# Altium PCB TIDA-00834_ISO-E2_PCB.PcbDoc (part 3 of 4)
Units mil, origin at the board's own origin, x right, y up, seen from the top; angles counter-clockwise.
Board outline 9055.12 x 4133.86 mil, 4 copper layers (Top Layer, GND, PWR, Bottom Layer), stack 61.92 mil thick; 647 components, 282 nets, 1430 pads, 409 vias.
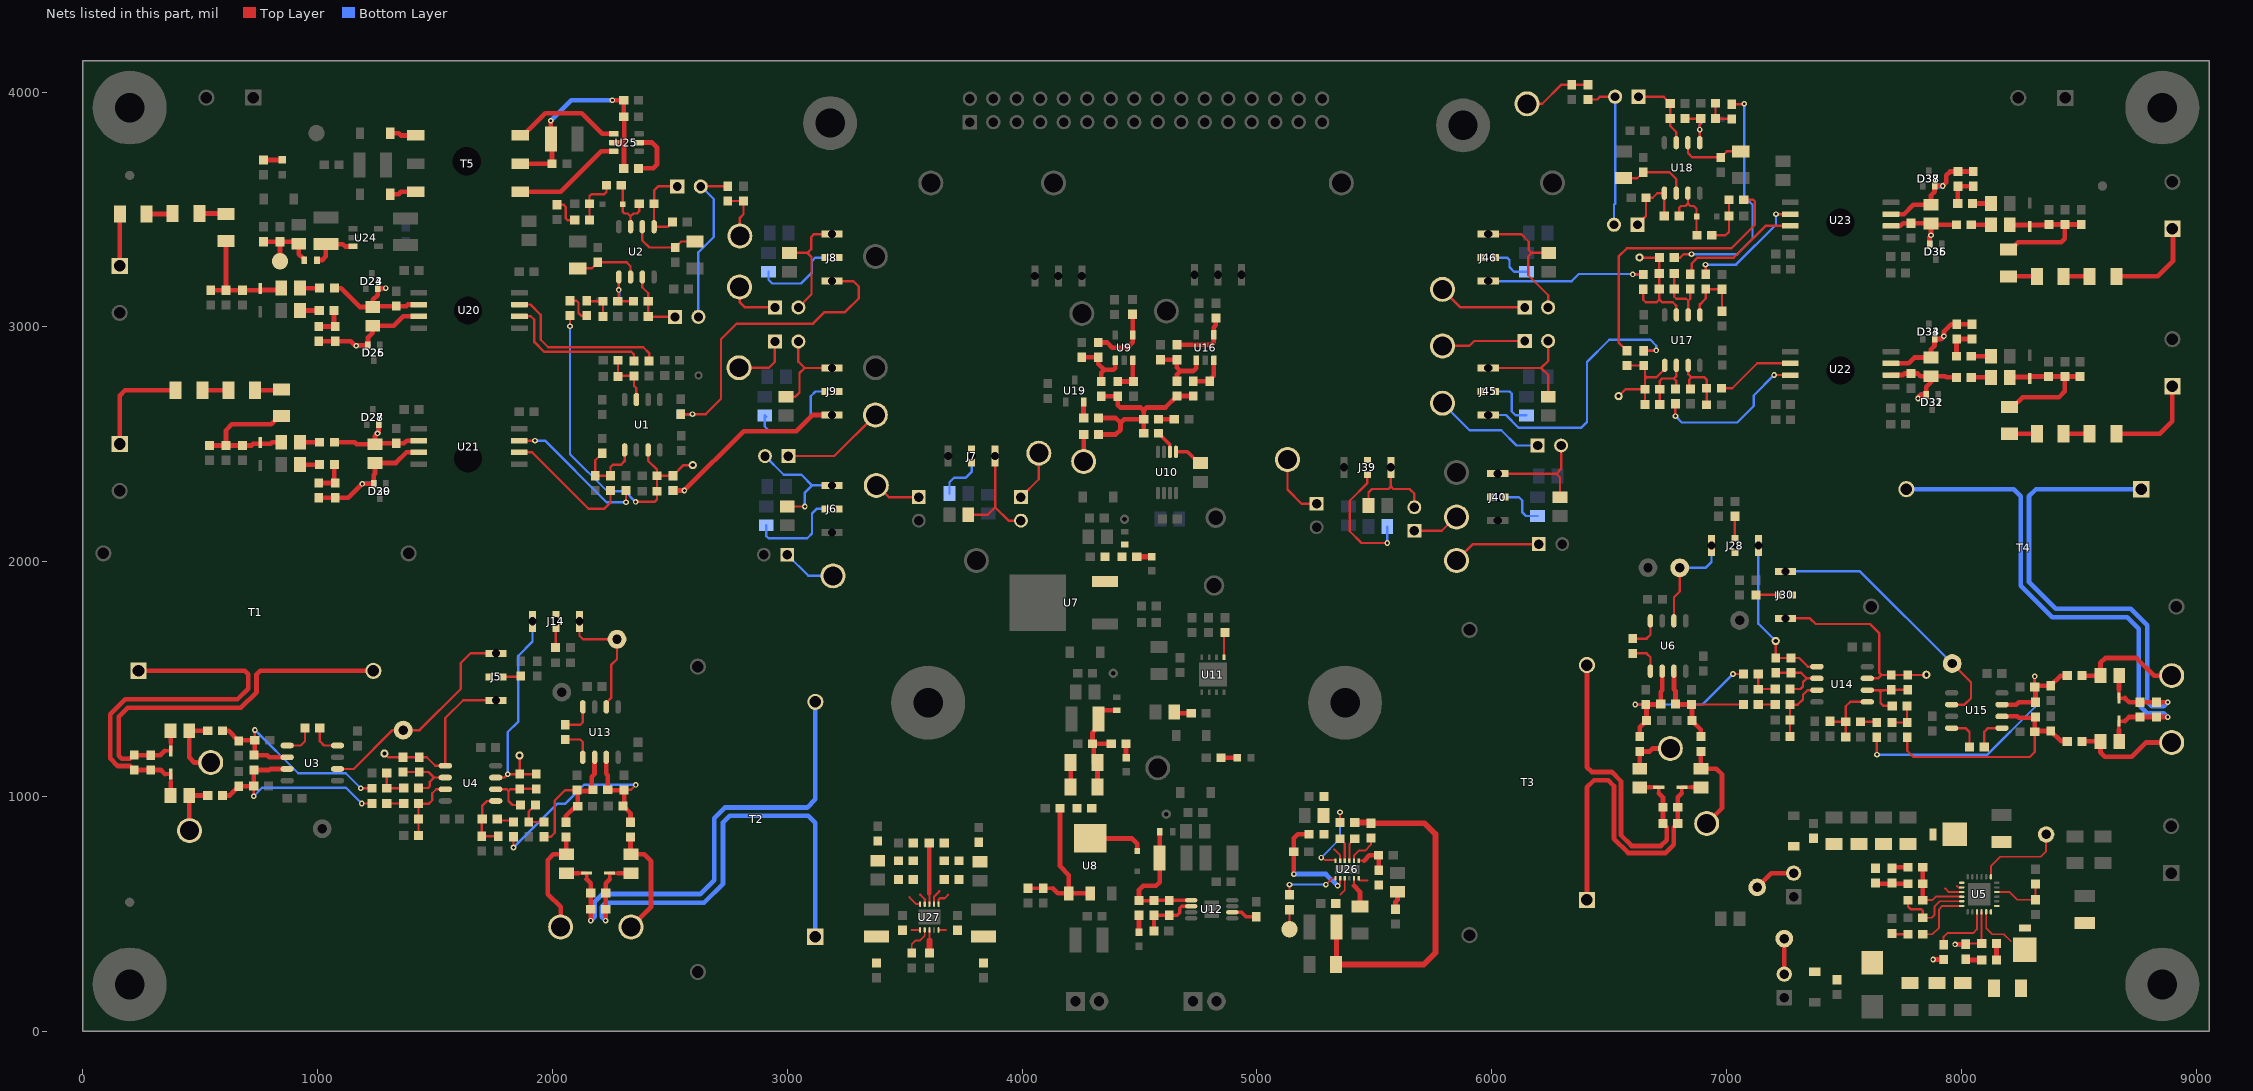
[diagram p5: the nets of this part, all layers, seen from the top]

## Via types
v1: diameter 24, hole 12, Top Layer to Bottom Layer, tented both sides, 388 vias
v2: diameter 19.68, hole 7.87, Top Layer to Bottom Layer, tented top, 15 vias
v3: diameter 19.68, hole 7.87, Top Layer to Bottom Layer, 5 vias
v4: diameter 40, hole 20, Top Layer to Bottom Layer, 1 vias

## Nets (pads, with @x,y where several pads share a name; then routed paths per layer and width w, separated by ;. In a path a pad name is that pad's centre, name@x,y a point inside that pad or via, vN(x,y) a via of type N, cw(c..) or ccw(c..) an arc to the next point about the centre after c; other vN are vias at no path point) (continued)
NetC2_2: C2.2 R3.1 R10.1 R230.2 TP4.1 U1.7 | length 1446.5
  Top Layer w10: v1(2075,3003) R230.2@2075,3048.5 ; v1(2354,2255) 2435,2255 2445,2265 R3.1@2445,2300 C2.2@2445,2366.3 ; U1.7@2407.38,2476.06 2407.38,2430.35 2445,2392.73 C2.2@2445,2366.3 ; TP4.1@2597.38,2411.49 2558.5,2411.49 R10.1@2513.5,2366.5 2513.31,2366.3 C2.2@2445,2366.3
  Bottom Layer w10: v1(2075,3003) 2075,2458 2233,2300 2309,2300 v1(2354,2255)
NetC7_2: C7.2 D1.1 L13.1 R11.1 R19.2 R20.2 | length 516.5
  Top Layer w20: R20.2@545,3156.5 R19.2@610,3156.5 ; R11.1@610,3365.83 R19.2@610,3156.5 ; C7.2@680,3156.5 C7.2@682.01,3156.5 ; L13.1@845,3165 837.02,3157.02 755.48,3157.02 754.95,3156.5 C7.2@682.01,3156.5 ; R19.2@610,3156.5 677.99,3156.5 680,3154.49 C7.2@682.01,3156.5
NetC8_2: C8.2 D2.1 L14.1 R16.1 R21.2 R22.2 | length 637.5
  Top Layer w20: R22.2@540,2495 R21.2@610,2495 ; L14.1@845,2508.5 807.01,2508.5 800.31,2501.81 725.31,2501.81 718.5,2495 C8.2@680,2495 R21.2@610,2495 ; R16.1@847.09,2619.92 836.85,2619.92 801.93,2585 635,2585 610,2560 R21.2@610,2495
NetC10_2: C10.2 R26.2 R27.1 | length 209.6
  Top Layer w10: R26.2@2157.97,3454.57 C10.2@2157.97,3524.57 2157.97,3556.89 2166.08,3565 2220,3565 2229.98,3574.98 R27.1@2229.98,3602.72
NetC11_2: C11.2 R32.2 R33.1 | length 134.1
  Top Layer w10: R32.2@2146.48,3111.07 2147.97,3109.57 R33.1@2214.98,3109.57 C11.2@2214.98,3044.57
NetC14_1: C14.1 C15.1 R35.2 R36.2 R57.2 U3.3 | length 949.7
  Top Layer w10: v1(727.91,1001.36) R36.2@727.91,1045.04 ; v1(1187.83,970.28) R57.2@1231.52,970.28
  Top Layer w20: R35.2@595,1005 625.86,1005 C14.1@664.41,1043.54 R36.2@726.41,1043.54 ; R36.2@727.91,1045.04 727.91,1112.05 C15.1@729.41,1113.54 794.41,1113.54 798.39,1117.52 U3.3@870.32,1117.52
  Bottom Layer w10: v1(727.91,1001.36) 764.74,1038.19 1119.92,1038.19 v1(1187.83,970.28)
NetC15_2: C15.2 C16.2 R40.1 R41.2 R62.2 U3.2 | length 1085
  Top Layer w10: C15.2@729.41,1176.53 729.41,1236.53 R40.1@732.91,1240.04 v1(732.91,1283.54) ; U3.2@866.81,1164.01 U3.2@870.32,1167.52 ; v1(1184.1,1035.28) R62.2@1231.52,1035.28
  Top Layer w20: R41.2@595,1280 620.94,1280 C16.2@664.41,1236.53 667.91,1240.04 R40.1@732.91,1240.04 C15.2@732.91,1180.04 ; C15.2@729.41,1176.53 786.06,1176.53 795.08,1167.52 U3.2@870.32,1167.52
  Bottom Layer w10: v1@732.91,1291.69 v1(732.91,1283.54) 917.26,1099.19 1120.18,1099.19 v1(1184.1,1035.28)
NetC19_1: C19.1 R43.2 R44.1 U4.2 | length 286.9
  Top Layer w10: R43.2@1363.09,1104.9 C19.1@1433.09,1104.9 1472.46,1104.9 1496.14,1081.22 ; R44.1@1429.59,1036.4 1470.22,1036.4 1478.09,1044.27 1478.09,1063.17 1496.14,1081.22 ; U4.2@1544,1081.22 1496.14,1081.22
NetC19_2: C19.2 J5.3 R43.1 TP10.1 U4.1 | length 731.4
  Top Layer w10: TP10.1@1284.41,1183.19 1299.7,1167.89 R43.1@1363.09,1167.89 C19.2@1433.09,1167.89 1464.47,1167.89 1501.14,1131.22 U4.1@1544,1131.22 1544,1334 1620,1410 J5.3@1760,1410
NetC25_1: C25.1 C27.1 C28.1 C29.1 C30.1 D5.1 J15.2 R58.2 R59.2 R60.2 TP15.1 | length 221
  Top Layer w8: R60.2@8017.64,307.83 R60.2@8021.14,304.33
  Top Layer w20: J15.2@7245.12,243.86 TP15.1@7245.12,394.88 ; R60.2@8021.14,304.33 R59.2@8086.14,304.33
NetC31_2: C31.2 R66.1 U5.17 | length 343.8
  Top Layer w8: C31.2@7835.12,483.86 7873.12,483.86 7885.12,495.86 7885.12,532.86 7906.39,554.13 U5.17@8000.79,554.13
  Top Layer w10: R66.1@7772.13,558.86 7772.13,531.85 7783.12,520.86 7827.89,520.86 7835.12,513.63 C31.2@7835.12,483.86
NetC32_1: C32.1 R59.1 | length 70
  Top Layer w20: R59.1@8149.13,304.33 C32.1@8149.13,374.33
NetC32_2: C32.2 R60.1 R61.1 U5.22 | length 287
  Top Layer w8: R60.1@8021.85,375.04 8085.43,375.04 U5.22@8085.43,508.86
  Top Layer w20: v1(7972.83,370.83) R60.1@8017.64,370.83
  Bottom Layer w20: v1(7972.83,370.83) R61.1@8017.64,370.83
NetC33_2: C33.2 R63.2 | length 65
  Top Layer w10: C33.2@7707.13,413.86 R63.2@7772.13,413.86
NetC34_1: C34.1 R67.1 | length 74.9
  Top Layer w10: R67.1@7703.62,695.35 R67.1@7707.13,698.86 ; C34.1@7768.62,695.35 C34.1@7772.13,698.86
  Top Layer w20: R67.1@7707.13,698.86 C34.1@7772.13,698.86
NetC34_2: C34.2 R64.1 R66.2 U5.16 | length 311.9
  Top Layer w8: R66.2@7835.12,558.86 7876.12,558.86 7891.08,573.82 U5.16@8000.79,573.82
  Top Layer w20: R66.2@7835.12,558.86 C34.2@7835.12,698.86
NetC35_1: C35.1 C36.1 C39.1 C40.1 C41.1 D6.2 D7.2 J16.2 R65.2 TP16.1 U5.15 | length 257
  Top Layer w8: 7930.12,608.86 7945.47,593.5 U5.15@8000.79,593.5
  Top Layer w20: TP16.1@7130,613.74 7190.12,673.86 J16.2@7285.12,673.86
NetC37_1: C37.1 R68.2 U5.4 | length 245.3
  Top Layer w8: U5.4@8150.39,593.5 8205.47,593.5 8238.15,560.83 C37.1@8315.12,560.83 R68.2@8315.12,627.83
NetC42_1: C42.1 R69.2 | length 89.6
  Top Layer w20: v1(7879.13,306.54) R69.2@7923.94,306.54
  Bottom Layer w20: v1(7879.13,306.54) C42.1@7923.94,306.54
NetC47_1: C47.1 C48.1 R106.2 R107.2 R113.2 U6.3 | length 586.7
  Top Layer w10: R107.2@6850.44,1392.36 R113.2@7071.55,1392.36
  Top Layer w20: U6.3@6775.43,1533.98 6775.43,1456.69 6781.93,1450.19 C48.1@6781.93,1393.86 6783.43,1392.36 R107.2@6850.44,1392.36 6851.93,1390.87 C47.1@6851.93,1323.86 6890.12,1285.67 R106.2@6890.12,1255.35 ; R113.2@7071.55,1392.36 R113.2@7071.71,1392.2
NetC48_2: C48.2 C52.2 R111.1 R112.2 R114.2 U6.2 | length 917.4
  Top Layer w10: v1(6610.44,1392.36) R111.1@6655.44,1392.36 ; v1(7026.71,1522.2) R114.2@7071.71,1522.2
  Top Layer w20: R112.2@6630.12,1255.35 6630.12,1295.04 C52.2@6658.94,1323.86 6658.94,1388.86 R111.1@6655.44,1392.36 6717.44,1392.36 C48.2@6718.94,1393.86 6718.94,1445.83 6725.43,1452.32 U6.2@6725.43,1533.98
  Bottom Layer w10: v1(6610.44,1392.36) 6896.87,1392.36 v1(7026.71,1522.2)
NetC49_1: C49.1 FB1.1 R71.2 U7.3
NetC54_1: C54.1 C59.1 C60.1 D45.2 FB2.1 R74.2 R75.2 R76.2 U8.4 | length 734.8
  Top Layer w20: U8.4@4290,822.3 4291.15,821.15 4468.85,821.15 4490,800 D45.2@4490,768.31 ; R76.2@4321,1051 4321,1126.91 4305,1142.91 4305,1219.41 C59.1@4299.41,1225 ; R74.2@4379.41,1225 C59.1@4299.41,1225 ; FB2.1@4402.91,1367.44 4325,1367.44 C60.1@4325,1330 4325,1297.09 4299.41,1271.5 C59.1@4299.41,1225
NetC54_2: C54.2 C166.1 R75.1 R76.1 R79.2 R80.2 U8.1 U8.2 | length 752.8
  Top Layer w15: R80.2@4025,610 R79.2@4090,610 4130,610
  Top Layer w20: 4130,610 4152.2,587.8 U8.1@4199,587.8 ; C166.1@4161.5,950 4161.5,703.5 4199,666 U8.1@4199,587.8 ; R76.1@4205.83,1044.17 R76.1@4205.83,1055.32 ; R76.1@4206.91,1055.32 R75.1@4206.91,1145 ; U8.2@4290,587.8 U8.1@4199,587.8
NetC61_1: C61.1 U10.5 | length 123.7
  Top Layer w15: U10.5@4654.98,2467.6 4704,2467.6 4751.6,2420 C61.1@4759,2420
NetC63_2: C63.2 R78.1 U9.3 | length 157.7
  Top Layer w20: R78.1@4407.15,2767.75 C63.2@4474,2767.75 4471.4,2770.35 U9.3@4471.4,2857.55
NetC64_1: C64.1 R81.2 | length 67
  Top Layer w20: R81.2@4580.5,2607 C64.1@4647.5,2607
NetC70_1: C70.1 R85.1 R86.2 U12.2 | length 252.7
  Top Layer w15: R86.2@4561.21,427.75 4561.44,427.99 R85.1@4561.44,494.26 C70.1@4626.44,494.26 4660.44,494.26 4671.44,505.26 4671.44,525.26 4679.24,533.06 U12.2@4719.8,533.06
NetC70_2: C70.2 C72.2 FB3.1 R84.2 R85.2 U12.1 | length 584.2
  Top Layer w15: R84.2@4497.71,557.25 R85.2@4561.44,557.25 4562.84,558.65 U12.1@4719.8,558.65
  Top Layer w20: R84.2@4497.71,557.25 4497.71,602.71 4515,620 4570,620 4585.62,635.62 C72.2@4585.62,737.75 FB3.1@4585.62,850.13
NetC73_1: C73.1 R83.1 | length 74.3
  Top Layer w20: C73.1@4647.4,1360 4652.4,1355 R83.1@4719.61,1355
NetC74_2: C74.2 U12.6 | length 109.2
  Top Layer w15: U12.6@4895,507.47 4934.24,507.47 4952.94,488.77 C74.2@4996.44,488.77
NetC77_1: C77.1 C78.1 R89.2 R90.2 R104.2 U13.3 | length 1098.1
  Top Layer w10: v1(1834.41,783.19) R104.2@1834.41,828.6 ; R90.2@2304.41,1027.59 2305.91,1029.09 2334.09,1029.09 v1(2355,1050)
  Top Layer w20: U13.3@2229.41,1167.36 2229.41,1097.02 2235.91,1090.53 C78.1@2235.91,1029.09 2237.4,1027.59 R90.2@2304.41,1027.59 2305.91,1026.1 C77.1@2305.91,959.09 ; C77.1@2300.91,960.04 2332.35,928.6 R89.2@2332.35,890.58
  Bottom Layer w10: v1(1834.41,783.19) 2021.22,970 2055,970 2135,1050 v1(2355,1050)
NetC78_2: C78.2 C79.2 R94.1 R95.2 R105.2 U13.2 | length 670.5
  Top Layer w10: R105.2@1964.41,828.54 1992.54,828.54 2010,846 2010,983.18 2054.41,1027.59 R94.1@2104.41,1027.59
  Top Layer w20: R95.2@2057.35,890.58 2057.35,917.35 2099.09,959.09 C79.2@2107.92,959.09 2107.92,1024.09 2167.92,1024.09 2167.92,1084.66 2179.41,1096.15 U13.2@2179.41,1167.36
NetC82_1: C82.1 R97.2 R98.1 U4.6 | length 280.2
  Top Layer w10: U4.6@1758.57,1031.22 1806.14,1031.22 1813.09,1024.27 ; R98.1@1864.45,964.27 1830.09,964.27 1813.09,981.27 1813.09,1024.27 ; R97.2@1930.94,1032.78 C82.1@1860.94,1032.78 1859.44,1031.27 1820.09,1031.27 1813.09,1024.27
NetC82_2: C82.2 J14.3 R97.1 TP30.1 U4.7 | length 952.7
  Top Layer w10: U4.7@1758.57,1081.22 1796.22,1081.22 v1(1810,1095) 1860.18,1095 C82.2@1860.94,1095.77 ; TP30.1@1860,1175 1860.94,1174.06 C82.2@1860.94,1095.77 ; R97.1@1930.94,1095.77 C82.2@1860.94,1095.77
  Bottom Layer w10: v1(1810,1095) 1810,1275 1855,1320 1855,1600 1915,1660 J14.3@1915,1746.14
NetC88_1: C88.1 R115.2 R117.1 U14.2 | length 285.9
  Top Layer w10: R115.2@7208.82,1527.36 7272.76,1527.36 C88.1@7273.29,1526.83 7317.15,1526.83 7340.83,1503.15 ; R117.1@7269.78,1458.32 7314.58,1458.32 7325.12,1468.86 7325.12,1487.44 7340.83,1503.15 ; U14.2@7384.2,1503.15 7340.83,1503.15
NetC88_2: C88.2 J28.3 R115.1 TP28.1 U14.1 | length 699.8
  Top Layer w10: TP28.1@7208.82,1662.56 R115.1@7208.82,1590.35 7209.35,1589.82 C88.2@7273.29,1589.82 7309.15,1589.82 7345.83,1553.15 U14.1@7384.2,1553.15
  Bottom Layer w10: J28.3@7135.12,2068.86 7135.12,1736.26 TP28.1@7208.82,1662.56
NetC94_1: C94.1 C95.1 R122.2 R123.2 R129.2 U15.3 | length 1377.4
  Top Layer w10: R129.2@7638.82,1252.36 7638.82,1180.16 v1(7640.12,1178.86) ; R123.2@8311.61,1466.65 v1(8311.61,1511.65)
  Top Layer w20: U15.3@8172.4,1391.65 8232.91,1391.65 8243.43,1402.17 C95.1@8315.12,1402.17 8315.12,1463.15 R123.2@8311.61,1466.65 8317.13,1472.17 C94.1@8380.12,1472.17 8380.12,1473.39 8421.73,1515 R122.2@8450,1515
  Bottom Layer w10: v1(7640.12,1178.86) 8110.12,1178.86 8311.61,1380.35 v1(8311.61,1511.65)
NetC95_2: C95.2 C96.2 R127.1 R128.2 R130.2 U15.2 | length 1064.9
  Top Layer w10: R130.2@7768.82,1252.36 7768.82,1195.16 7795.12,1168.86 8290.12,1168.86 8311.61,1190.35 R127.1@8311.61,1275.67
  Top Layer w20: U15.2@8172.4,1341.65 8237.32,1341.65 8243.31,1335.67 8311.61,1335.67 R127.1@8311.61,1275.67 8315.12,1279.18 C96.2@8380.12,1279.18 8424.3,1235 R128.2@8450,1235
NetC99_1: C99.1 R131.2 R133.1 U14.6 | length 299.1
  Top Layer w10: U14.6@7598.77,1453.15 7664.41,1453.15 ; 7645.83,1453.15 7655.12,1443.86 ; R133.1@7704.65,1386.2 7667.78,1386.2 7655.12,1398.86 7655.12,1443.86 ; R131.2@7771.14,1454.7 C99.1@7701.14,1454.7 7699.59,1453.15 7664.41,1453.15 ; 7655.12,1443.86 7664.41,1453.15
NetC99_2: C99.2 J30.3 R131.1 TP41.1 U14.7 | length 865.2
  Top Layer w10: J30.3@7250.12,1758.86 7355,1758.86 7378.86,1735 7610,1735 7650.12,1694.88 7650.12,1526.53 7658.95,1517.69 ; U14.7@7598.77,1503.15 7644.41,1503.15 7658.95,1517.69 ; TP41.1@7850.12,1518.86 7848.95,1517.69 R131.1@7771.14,1517.69 C99.2@7701.14,1517.69 7658.95,1517.69
NetC101_1: C101.1 R138.2 R143.1 U17.2 | length 275.5
  Top Layer w10: R138.2@6714.86,2669.33 C101.1@6714.86,2734.33 6714.86,2769.86 6725,2780 6775,2780 ; R143.1@6781.71,2735.82 6785,2739.11 6785,2770 6775,2780 ; U17.2@6785.96,2836.42 6785.96,2790.96 6775,2780
NetC101_2: C101.2 R138.1 R145.1 R200.2 TP44.1 U17.1 | length 487.2
  Top Layer w10: TP44.1@6540,2705 6569.33,2734.33 C101.2@6651.87,2734.33 ; R200.2@6575,2835.55 R145.1@6647.26,2835.55 ; R138.1@6651.87,2669.33 C101.2@6651.87,2734.33 ; 6651.87,2793.13 6660,2785 ; R145.1@6651.87,2830.94 6651.87,2776.87 ; U17.1@6735.96,2836.42 6735.96,2820.96 6700,2785 6660,2785 ; C101.2@6651.87,2734.33 6651.87,2776.87 ; 6651.87,2776.87 6660,2785
NetC102_1: C102.1 R140.2 R146.1 U17.6 | length 278.9
  Top Layer w10: R140.2@6776.33,3227.04 C102.1@6776.33,3160.74 6776.33,3128.67 6785,3120 6826.91,3120 6835.96,3110.96 ; U17.6@6835.96,3050.98 6835.96,3110.96 ; R146.1@6844.84,3160.86 6844.84,3119.84 6835.96,3110.96
NetC102_2: C102.2 R140.1 R147.1 R201.2 TP45.1 U17.7 | length 508.4
  Top Layer w10: TP45.1@6629,3296 6630,3295 R201.2@6713.5,3295 6713.34,3294.84 R140.1@6713.34,3227.04 C102.2@6713.34,3160.74 6713.34,3116.66 ; R147.1@6644.84,3160.55 6644.84,3115.16 6655,3105 6701.68,3105 6713.34,3116.66 ; U17.7@6785.96,3050.98 6785.96,3089.04 6770,3105 6725,3105 6713.34,3116.66
NetC107_2: C107.2 D17.1 L17.1 R148.1 R156.2 R157.2 | length 627.2
  Top Layer w20: R148.1@8205,2659.17 8219.17,2659.17 8260,2700 8415,2700 8440,2725 R156.2@8440,2788.5 ; L17.1@8205,2785 8206.69,2786.69 8290,2786.69 8291.81,2788.5 C107.2@8370,2788.5 R156.2@8440,2788.5 ; R157.2@8505,2788.5 R156.2@8440,2788.5
NetC108_2: C108.2 D18.1 L18.1 R153.1 R158.2 R159.2 | length 623.4
  Top Layer w20: R153.1@8199.96,3329.61 8210.2,3329.61 8240.59,3360 8425,3360 8440,3375 R158.2@8440,3435.98 ; L18.1@8205,3435 8205.83,3434.17 C108.2@8371.14,3434.17 ; C108.2@8372.95,3435.98 R158.2@8440,3435.98 ; R159.2@8510,3435.98 R158.2@8440,3435.98
NetC109_2: C109.2 R163.2 R164.1 | length 216.2
  Top Layer w10: R164.1@6936.5,3390 6995,3390 7009.63,3404.63 C109.2@7009.63,3471.84 R163.2@7009.63,3541.68
NetC111_2: C111.2 R169.2 R170.1 | length 134.2
  Top Layer w10: C111.2@6952.62,3951.84 R170.1@6952.62,3886.84 7019.47,3886.84 R169.2@7021.12,3885.19
NetC117_2: C117.2 R192.1 U16.3 | length 166.6
  Top Layer w20: R192.1@4729,2768.5 C117.2@4799,2768.5 4799,2775 4816.4,2792.4 U16.3@4816.4,2857.87
NetC120_2: C120.2 R196.2 TP31.1 | length 222.4
  Top Layer w10: R196.2@2746.48,3536.22 2813.09,3536.22 C120.2@2813.52,3535.79 2813.52,3479.52 2798,3464 TP31.1@2798,3387
NetC121_2: C121.2 R197.2 TP46.1 | length 293.8
  Top Layer w10: TP46.1@6150,3950 6215,3950 6296.5,4031.5 C121.2@6340,4031.5 R197.2@6410,4031.5
NetC126_1: C126.1 D23.1 D24.2 R205.1 R206.2 U20.2 | length 553.3
  Top Layer w20: R206.2@1071.5,3165 1100,3165 1180,3085 C126.1@1235,3085 ; v1(1290,3165) 1288.5,3163.5 D24.2@1255.59,3163.5 1255.59,3135.59 1235,3115 C126.1@1235,3085 ; U20.2@1430.43,3095 1385,3095 1378.5,3088.5 R205.1@1335,3088.5 1238.5,3088.5 C126.1@1235,3085
  Bottom Layer w20: D23.1@1255.59,3163.5 1257.09,3165 v1(1290,3165)
NetC126_2: C126.2 D25.2 D26.1 R208.1 R209.1 U20.3 | length 571.8
  Top Layer w20: R208.1@1005,2938.5 R209.1@1075,2938.5 1141.5,2938.5 1160,2920 1161.5,2921.5 D25.2@1214.41,2921.5 1214.41,2954.41 1235,2975 C126.2@1235,3005 1325,3005 1365,3045 U20.3@1430.43,3045
  Bottom Layer w20: v1(1165,2920) 1166.5,2921.5 D26.1@1214.41,2921.5
NetC131_1: C131.1 D27.1 D28.2 R199.1 R210.2 U21.2 | length 497.8
  Top Layer w20: R210.2@1071.5,2508.5 1157.99,2508.5 1165.87,2500.63 C131.1@1244.61,2500.63 ; D28.2@1260.2,2584.13 1260.2,2551.69 v1(1255,2546.5) 1244.61,2536.1 C131.1@1244.61,2500.63 ; U21.2@1430.04,2515.63 1379.13,2515.63 1367.64,2504.13 R199.1@1334.61,2504.13 1248.11,2504.13 C131.1@1244.61,2500.63
  Bottom Layer w20: v1(1255,2546.5) 1260.2,2551.69 D27.1@1260.2,2584.13
NetC131_2: C131.2 D29.2 D30.1 R212.1 R213.1 U21.3 | length 603.1
  Top Layer w20: R213.1@1005,2272.01 R212.1@1075,2272.01 1130.51,2272.01 v1(1190,2331.5) 1190.63,2332.13 D29.2@1239.02,2332.13 1239.02,2370.02 1244.61,2375.61 C131.2@1244.61,2420.63 1333.63,2420.63 1378.63,2465.63 U21.3@1430.04,2465.63
  Bottom Layer w20: v1(1190,2331.5) 1238.39,2331.5 D30.1@1239.02,2332.13
NetC136_1: C136.1 D31.1 D32.2 R215.1 R216.2 U22.2 | length 463.8
  Top Layer w20: U22.2@7699.57,2795 7750,2795 7756.5,2801.5 R215.1@7785,2801.5 7813.5,2801.5 7825,2790 C136.1@7870,2790 ; v1(7815,2695) 7815,2700 7826.5,2711.5 D32.2@7849.41,2711.5 7849.41,2744.41 7870,2765 C136.1@7870,2790 ; R216.2@7978.5,2785 7935,2785 7930,2790 C136.1@7870,2790
  Bottom Layer w20: v1(7815,2695) 7815,2700 7825,2710 7847.91,2710 D31.1@7849.41,2711.5
NetC136_2: C136.2 D33.2 D34.1 R218.1 R219.1 U22.3 | length 507.6
  Top Layer w20: U22.3@7699.57,2845 7775,2845 7800,2870 C136.2@7870,2870 7870,2905 7885.28,2920.28 D33.2@7885.28,2948.5 7913.5,2948.5 v1(7925,2960) 7925,2980 7956.5,3011.5 R218.1@7980,3011.5 R219.1@8045,3011.5
  Bottom Layer w20: D34.1@7885.28,2948.5 7886.77,2950 7915,2950 v1(7925,2960)
NetC141_1: C141.1 D35.1 D36.2 R221.1 R222.2 U23.2 | length 418
  Top Layer w20: U23.2@7699.57,3430 7740,3430 7751.5,3441.5 R221.1@7785,3441.5 7868.5,3441.5 C141.1@7870,3440 ; D36.2@7864.41,3351.5 7864.41,3384.41 v1(7870,3390) C141.1@7870,3440 ; R222.2@7978.5,3435 7875,3435 C141.1@7870,3440
  Bottom Layer w20: D35.1@7864.41,3351.5 7864.41,3384.41 v1(7870,3390)
NetC141_2: C141.2 D37.2 D38.1 R224.1 R225.1 U23.3 | length 516.2
  Top Layer w20: U23.3@7699.57,3480 7755,3480 7795,3520 C141.2@7870,3520 7870,3560 7885.28,3575.28 D37.2@7885.28,3600.32 v1@7919.68,3600.32 ; v1(7920,3600) 7935,3615 7935,3645.5 7951,3661.5 R224.1@7985,3661.5 R225.1@8050,3661.5
  Bottom Layer w20: D38.1@7885.28,3600.32 7885.6,3600 v1(7920,3600)
NetC144_2: C144.2 C145.1 L19.2 R226.1 TP57.1 | length 313.8
  Top Layer w20: R226.1@770,3362.97 C145.1@840,3362.97 ; TP57.1@840,3279.47 C145.1@840,3362.97 ; L19.2@942.44,3287.03 920,3309.47 C144.2@920,3354.47 911.5,3362.97 C145.1@840,3362.97
NetC146_2: C146.2 L19.1 U24.3 | length 216.2
  Top Layer w20: L19.1@997.56,3284.47 1019.47,3284.47 1035,3300 C146.2@1035,3352.38 1107.62,3352.38 1117.4,3342.6 U24.3@1150.87,3342.6
NetC147_2: C147.2 C148.2 C167.2 R228.1 R244.1 T5.2 U25.2 | length 999.3
  Top Layer w20: T5.2@1862.64,3695 C148.2@1998.5,3695 1998.5,3795.59 1993.5,3800.59 C147.2@1992.91,3800 v1(1992.91,3877.91) ; v1(2255.24,3965) R228.1@2303.5,3965 C167.2@2303.5,3895 2306,3892.5 2306,3797 2294,3785 2305,3774 2305,3676.5 R244.1@2303.5,3675 ; U25.2@2260.87,3785 2290,3785
  Bottom Layer w20: v1(1992.91,3877.91) 2080,3965 v1(2255.24,3965)
NetC151_2: C151.2 C152.1 R214.1 R231.1 R245.1 U26.3 | length 1551.9
  Top Layer w8: 5354.5,582 5373.82,601.32 U26.3@5373.82,652.44
  Top Layer w20: R245.1@5337.09,285 5338.5,286.42 C151.2@5338.5,445 ; R231.1@5481.5,890 R231.1@5485,886.5
  Top Layer w25: R245.1@5337.09,285 5710,285 5760,335 5760,840 5713.5,886.5 R231.1@5485,886.5 ; R214.1@5416.5,890 R231.1@5481.5,890
NetC153_1: C153.1 R198.1 R202.2 U26.11 | length 58.4
  Top Layer w8: 5328.5,775 5354.13,749.37 U26.11@5354.13,727.24
NetC154_1: C154.1 U26.9 | length 102.3
  Top Layer w9: U26.9@5393.5,727.24 5393.5,797.01 C154.1@5416.5,820
NetC154_2: C154.2 U26.10 | length 101.2
  Top Layer w9: C154.2@5353.5,820 5373.82,799.69 U26.10@5373.82,727.24
NetC155_1: C155.1 R204.2 R233.1 U26.6 | length 128.5
  Top Layer w9: U26.6@5432.87,652.44 5432.87,649.13 5440,642 5471,642
  Top Layer w20: R204.2@5514.57,627.44 R204.2@5518.5,623.5 ; R233.1@5590,520 5590,551.5 5598.5,560 C155.1@5598.5,595
NetC156_1: C156.1 U26.5 | length 130.8
  Top Layer w8: 5413.19,620.31 U26.5@5413.19,652.44
  Top Layer w20: 5413.19,620.31 5438.5,595 C156.1@5438.5,532.09
NetC157_2: C157.2 C158.1 R246.2 U27.1 | length 43
  Top Layer w8: 3529,431.97 U27.1@3565.63,431.97
  Top Layer w25: C158.1@3485.59,430.59 C158.1@3490,430.59 C158.1@3491.38,431.97
NetC159_1: C159.1 C160.1 R234.1 R235.2 U27.10 | length 58
  Top Layer w9: 3520,572.09 3549.88,542.2 U27.10@3565.63,542.2
NetC159_2: C159.2 R235.1 R237.2 U27.9 | length 47.9
  Top Layer w9: 3566,582.09 3585.31,562.77 U27.9@3585.31,542.2
NetC161_1: C161.1 C162.1 R236.2 R240.1 U27.6 | length 68.4
  Top Layer w9: U27.6@3644.37,542.2 3644.37,561.46 3650,567.09 3670,567.09 3685,582.09
NetC161_2: C161.2 R236.1 R239.2 U27.7 | length 65.1
  Top Layer w9: U27.7@3624.69,542.2 3624.69,573.77 3647,596.09 3647,598.09
NetC163_1: C163.1 U27.3 | length 98.4
  Top Layer w9: 3605,387.09 U27.3@3605,431.97
  Top Layer w25: C163.1@3605,333.58 3605,387.09
NetC164_2: C164.2 C165.1 R247.2 U27.5 | length 30.5
  Top Layer w9: U27.5@3644.37,431.97 3674.88,431.97
NetD3_1: D3.1 L1.1 R37.2 R39.2 T1.1 | length 1730.5
  Top Layer w15: 348.82,1096.14 D3.1@374.41,1096.14 374.41,1062
  Top Layer w20: T1.1@237.6,1535.51 689.49,1535.51 705,1520 705,1460 659,1414 181,1414 117.64,1350.64 117.64,1162.36 150,1130 202.95,1130 R37.2@219.41,1113.54 R37.2@219.41,1113.54 R39.2@290,1113.5 331.46,1113.5 348.82,1096.14 ; L1.1@373.5,1005 374.41,1005.91 374.41,1062
NetD3_2: D3.2 L2.1 R37.1 R39.1 T1.2 | length 1718.2
  Top Layer w15: 348.82,1194.57 D3.2@374.41,1194.57 374.41,1228.59
  Top Layer w20: 348.82,1194.57 330.75,1176.5 R39.1@290,1176.5 R37.1@219.41,1176.54 R37.1@219.41,1176.54 216.54,1176.54 201,1161 166,1161 153,1174 153,1340.64 191,1378.64 673.64,1378.64 740,1445 740,1520 755.51,1535.51 T1.2@1237.6,1535.51 ; L2.1@362.33,1291.18 L2.1@373.51,1280 374.41,1279.1 374.41,1228.59
NetD4_1: D4.1 R58.1 U5.23 | length 198.3
  Top Layer w8: U5.23@8105.12,508.86 8105.12,438.86 8130.12,413.86 8180.62,413.86 8210.62,383.86
NetD4_2: D4.2 L3.2 U5.1 U5.24
NetD7_1: D7.1 L4.1 U5.13 U5.14 | length 23
  Top Layer w8: 7980.12,618.86 7985.79,613.19 U5.14@8000.79,613.19
NetD9_1: D9.1 L7.1 R108.2 R110.2 T3.1 | length 1477.7
  Top Layer w15: 6809.21,1014.41 D9.1@6809.21,1040 6848.98,1040
  Top Layer w20: T3.1@6405,560 6405,1040 6435,1070 6495,1070 6520,1045 6520,820 6580,760 6740,760 6775,795 6775,868.5 R108.2@6791.5,885 R110.2@6791.5,955 6791.5,996.5 6809.21,1014.21 6809.21,1014.41 ; 6848.98,1040 6888.98,1040 L7.1@6890.12,1038.86
NetD9_2: D9.2 L8.1 R108.1 R110.1 T3.2 | length 1379.2
  Top Layer w15: 6680,1040 D9.2@6710.79,1040 6710.79,1014.21
  Top Layer w20: T3.2@6405,1560 6405,1125 6425,1105 6510,1105 6550,1065 6550,835 6595,790 6720,790 6745,815 6745,868.5 R108.1@6728.5,885 R110.1@6728.5,955 6728.5,996.5 6710.79,1014.21 ; L8.1@6630.12,1038.86 6631.26,1040 6680,1040
NetD10_1: D10.1 R71.1 | length 64
  Top Layer w25: R71.1@4488.32,2021 4551.67,2021 D10.1@4552.14,2020.53
NetD12_1: D12.1 R74.1 | length 60.7
  Top Layer w20: R74.1@4442.4,1225 4442.4,1165.04 D12.1@4442.91,1164.53
NetD14_2: D14.2 R84.1 | length 72.2
  Top Layer w20: D14.2@4497.64,422.09 4497.71,422.16 R84.1@4497.71,494.26
NetD15_1: D15.1 L5.1 R91.2 R93.2 T2.1 | length 2087.3
  Top Layer w15: 2243.62,648.5 D15.1@2243.62,674.09 2277.91,674.09
  Top Layer w20: v1(2226.5,471.82) R91.2@2226.5,520 R93.2@2226.5,590 2226.5,631.37 2243.62,648.5 ; 2277.91,674.09 L5.1@2329.41,674.09 ; L5.1@2330.5,673 L5.1@2329.41,674.09 ; L5.1@2334.41,674.09 L5.1@2329.41,674.09
  Bottom Layer w20: v1(2226.5,471.82) 2210,488.31 2210,530 2228,548 2645.33,548 2726.41,629.08 2726.41,890.19 2754.41,918.19 3089.41,918.19 3119.41,888.19 T2.1@3119.41,403.19
NetD15_2: D15.2 L6.1 R91.1 R93.1 T2.2 | length 2072.4
  Top Layer w15: 2110.91,674.09 D15.2@2145.2,674.09 2145.2,648.5
  Top Layer w20: L6.1@2059.41,674.09 2110.91,674.09 ; 2145.2,648.5 2163.5,630.19 R93.1@2163.5,590 R91.1@2163.5,520 v1(2163.5,471.82)
  Bottom Layer w20: v1(2163.5,471.82) 2180,488.31 2180,552.33 2212.67,585 2630,585 2689.41,644.41 2689.41,908.19 2734.41,953.19 3084.41,953.19 3119.41,988.19 T2.2@3119.41,1403.19
NetD16_1: D16.1 L9.1 R124.2 R126.2 T4.1 | length 2174.9
  Top Layer w15: 8670.12,1455.58 D16.1@8670.12,1419.56 8695.71,1419.56
  Top Layer w20: 8670.12,1455.58 8670.12,1513.62 L9.1@8671.5,1515 ; 8695.71,1419.56 8713.78,1401.5 R126.2@8760,1401.5 R124.2@8830,1401.5 v1(8878.18,1401.5)
  Bottom Layer w20: T4.1@8765.12,2308.86 8317.12,2308.86 8287.12,2278.86 8287.12,1913.86 8400.98,1800 8721,1800 8791.06,1729.94 8791.06,1403.94 8810,1385 8861.69,1385 v1(8878.18,1401.5)
NetD16_2: D16.2 L10.1 R124.1 R126.1 T4.2 | length 2230.5
  Top Layer w15: 8670.12,1285.12 D16.2@8670.12,1321.14 8695.71,1321.14
  Top Layer w20: 8670.12,1285.12 8670.12,1236.38 L10.1@8671.5,1235 ; 8695.71,1321.14 8713.08,1338.5 R126.1@8760,1338.5 R124.1@8830,1338.5 v1(8878.18,1338.5)
  Bottom Layer w20: T4.2@7765.12,2308.86 8222.12,2308.86 8252.12,2278.86 8252.12,1897.86 8386.04,1763.94 8706.06,1763.94 8755,1715 8755,1390 8790,1355 8861.69,1355 v1(8878.18,1338.5)
NetD19_1: D19.1 R23.2 R27.2 U2.3 | length 278.7
  Top Layer w10: R27.2@2292.97,3602.72 2299.78,3595.9 D19.1@2299.78,3522.72 2299.78,3489.41 2306.48,3482.72 2320.56,3482.72 2332.59,3470.69 ; U2.3@2332.59,3426.85 2332.59,3470.69 ; R23.2@2369.98,3524.57 2369.98,3493.07 2359.62,3482.72 2344.62,3482.72 2332.59,3470.69
NetD20_1: D20.1 R29.2 R33.2 U2.5 | length 217.5
  Top Layer w10: U2.5@2282.59,3212.29 v1(2282.59,3157.72) 2282.59,3114.19 R33.2@2277.97,3109.57 R29.2@2344.98,3109.57
  Bottom Layer w10: v1(2282.59,3157.72) 2284.78,3155.52 D20.1@2284.78,3112.72
NetD21_1: D21.1 R160.2 R164.2 U18.3 | length 284.9
  Top Layer w10: R160.2@6797.78,3471.68 R160.2@6797.62,3471.84 6797.62,3507.62 6805,3515 6825,3515 6835,3525 ; U18.3@6835,3569.56 6835,3525 ; R164.2@6873.5,3390 6871.69,3391.81 D21.1@6871.69,3470 6871.69,3503.31 6860,3515 6845.01,3515 6835,3525
NetD22_1: D22.1 R166.2 R170.2 U18.5 | length 219.4
  Top Layer w10: R166.2@6822.62,3886.84 R170.2@6889.63,3886.84 6885,3882.22 U18.5@6885,3784.13
  Bottom Layer w10: v1(6885,3840) 6885,3860 6891.69,3866.69 D22.1@6891.69,3885
NetD40_2: D40.2 R227.1 | length 80.4
  Top Layer w20: R227.1@770,3710.96 849.02,3710.96 D40.2@850,3711.95
NetD41_2: D41.2 T5.6 | length 112
  Top Layer w20: D41.2@1309.47,3565 1345,3565 1354.92,3574.92 T5.6@1417.36,3574.92
NetD42_2: D42.2 T5.4 | length 112
  Top Layer w20: D42.2@1309.47,3825 1345,3825 1354.92,3815.08 T5.4@1417.36,3815.08
NetD44_1: D44.1 R241.1 | length 69
  Top Layer w20: R241.1@4846.5,1165 D44.1@4915.47,1165
NetJ1_1: J1.1 R2.2 | length 220.7
  Top Layer w20: J1.1@157.91,3260.16 R2.2@157.91,3480.91
NetJ2_1: J2.1 R4.2 | length 452.9
  Top Layer w20: J2.1@157.48,2501.38 157.48,2707.48 180,2730 R4.2@395,2730
NetJ3_1: J3.1 R23.1 R25.1 U2.1 | length 317.1
  Top Layer w10: J3.1@2501.48,3599.57 2451.48,3599.57 2432.97,3581.06 R23.1@2432.97,3524.57 2432.59,3524.19 U2.1@2432.59,3426.85 2491.73,3426.85 R25.1@2511.1,3446.22
NetJ3_2: J3.2 J4.2 R196.1 | length 721.7
  Top Layer w10: J3.2@2631.48,3599.57 2631.83,3599.21 R196.1@2746.48,3599.21
  Bottom Layer w10: J4.2@2621.48,3042.72 2621.48,3317.72 2686.48,3382.72 2686.48,3544.57 J3.2@2631.48,3599.57
NetJ4_1: J4.1 R29.1 R31.1 U2.7 | length 292.5
  Top Layer w10: U2.7@2382.59,3212.29 2382.59,3168.46 2407.97,3143.07 R29.1@2407.97,3109.57 R31.1@2407.97,3044.57 2409.83,3042.72 J4.1@2521.48,3042.72
NetJ5_1: J5.1 TP7.1 U3.6 | length 943.5
  Top Layer w10: U3.6@1084.88,1117.52 1153.74,1117.52 1319.41,1283.19 TP7.1@1364.41,1283.19 1434.41,1283.19 1609.41,1458.19 1609.41,1568.19 1651.22,1610 J5.1@1760,1610
NetJ5_2: J5.2 R45.1 | length 106.5
  Top Layer w10: J5.2@1760,1510 1861.5,1510 R45.1@1865,1513.5
NetJ6_1: J6.1 J20.2 R181.2 | length 514.2
  Top Layer w10: R181.2@3000,2235 v1(3075,2235)
  Bottom Layer w10: J20.2@2905,2450 2985,2370 3060,2370 3105,2325 ; v1(3075,2235) 3075,2295 3105,2325 ; J6.1@3190,2325 3105,2325
NetJ6_2: J6.2 R49.1 | length 430.7
  Bottom Layer w10: R49.1@2910,2155 2910,2110 2920,2100 3085,2100 3105,2120 3105,2205 3125,2225 J6.2@3190,2225
NetJ7_1: J7.1 J21.2 R182.2 | length 478.8
  Top Layer w10: R182.2@3771,2200 3852.85,2200 3885,2232.15 ; J7.1@3885,2450 3885,2232.15 ; J21.2@3995,2175.03 3942.12,2175.03 3885,2232.15
NetJ7_2: J7.2 R50.1 | length 228.2
  Bottom Layer w10: R50.1@3691,2290 3691,2338.15 3711,2358.15 3761,2358.15 3785,2382.15 J7.2@3785,2450
NetJ8_1: J8.1 J17.2 R188.2 | length 505.8
  Top Layer w10: R188.2@3010,3315 3086,3315 ; J17.2@3047,3083 3103,3139 3103,3298 3086,3315 ; J8.1@3190,3395 3114,3395 3102,3383 3102,3331 3086,3315
NetJ8_2: J8.2 R53.1 | length 385.5
  Bottom Layer w10: R53.1@2920,3235 2920,3201 2936,3185 3059,3185 3105,3231 3105,3281 3119,3295 J8.2@3190,3295
NetJ9_1: J9.1 J18.2 R185.2 | length 418.5
  Top Layer w10: R185.2@2994.43,2703.05 3034.43,2703.05 3052,2720.62 3052,2803 3074,2825 ; J18.2@3047,2938 3047,2852 3074,2825 ; J9.1@3190,2825 3074,2825
NetJ9_2: J9.2 R54.1 | length 472
  Bottom Layer w10: R54.1@2910,2617.49 R54.1@2904.43,2623.05 2904.43,2575.57 2925,2555 3039,2555 3100,2616 3100,2705 3120,2725 J9.2@3190,2725
NetJ14_1: J14.1 TP27.1 U13.6 | length 534.3
  Top Layer w10: J14.1@2115,1746.14 2115,1685 2130,1670 TP27.1@2275,1670 2275,1585 2250,1560 2250,1420 2229.41,1399.41 U13.6@2229.41,1381.92
NetJ14_2: J14.2 R99.1 | length 111.8
  Top Layer w10: R99.1@2013.5,1635 2013.5,1744.65 J14.2@2015,1746.14
NetJ17_1: J17.1 TP13.1 | length 223.5
  Top Layer w10: TP13.1@2797,3170 2797,3106 2820,3083 J17.1@2947,3083
NetJ18_1: J18.1 TP14.1 | length 250.4
  Top Layer w10: TP14.1@2794,2826 2922,2826 2947,2851 J18.1@2947,2938
NetJ20_1: J20.1 TP11.1 | length 446.5
  Top Layer w10: J20.1@3005,2450 3200,2450 TP11.1@3375,2625 TP11.1@3379,2625
NetJ21_1: J21.1 TP12.1 | length 226.5
  Top Layer w10: J21.1@3995,2275.03 4071,2351.03 TP12.1@4071,2462.15 TP12.1@4071,2470
NetJ22_1: J22.1 TP18.1 | length 232.3
  Bottom Layer w10: J22.1@3000,2030 3090,1940 TP18.1@3195,1940
NetJ23_1: J23.1 TP35.1 | length 201.5
  Top Layer w10: TP35.1@3380,2327 3431.97,2275.03 J23.1@3560,2275.03
NetJ24_1: J24.1 TP52.1 | length 361.5
  Top Layer w10: TP52.1@5789,2919 TP52.1@5791,2917 ; TP52.1@5790,2919 5904,2919 5925,2940 J24.1@6140,2940
NetJ24_2: J24.2 J45.1 R186.2 | length 486.8
  Top Layer w10: J45.1@5985,2825 6210,2825 ; R186.2@6240,2703.05 6240,2795 6210,2825 ; J24.2@6240,2940 6240,2855 6210,2825
NetJ25_1: J25.1 TP51.1 | length 381.9
  Top Layer w10: TP51.1@5790,3160 5867,3083 J25.1@6140,3083
NetJ25_2: J25.2 J46.1 R187.2 | length 584.4
  Top Layer w10: J46.1@5985,3395 6125,3395 6157.38,3362.62 6157.38,3327.62 6170,3315 ; J25.2@6240,3083 6240,3135 6155,3220 6155,3300 6170,3315 ; R187.2@6242.38,3315 6170,3315
NetJ28_1: J28.1 TP8.1 U6.6 | length 450.9
  Top Layer w10: U6.6@6775.43,1748.54 6775.43,1849.17 6800.12,1873.86 TP8.1@6800.12,1973.86
  Bottom Layer w10: TP8.1@6800.12,1973.86 6910.12,1973.86 6935.12,1998.86 J28.1@6935.12,2068.86
NetJ28_2: J28.2 R118.1 | length 124.7
  Top Layer w10: R118.1@7035,2193.5 7035,2068.98 J28.2@7035.12,2068.86
NetJ30_1: J30.1 TP39.1 U15.6 | length 1146.9
  Top Layer w10: U15.6@7957.83,1391.65 8012.91,1391.65 8040.12,1418.86 8040.12,1486.65 TP39.1@7960.12,1566.65
  Bottom Layer w10: J30.1@7250.12,1958.86 7567.91,1958.86 TP39.1@7960.12,1566.65
NetJ30_2: J30.2 R134.1 | length 127
  Top Layer w10: R134.1@7125,1863.5 7129.65,1858.86 J30.2@7250.12,1858.86
NetJ31_1: J31.1 R139.2 | length 409.9
  Top Layer w20: R139.2@8660,2545 8845,2545 8897.64,2597.64 J31.1@8897.64,2747.48 J31.1@8897.2,2747.05
NetJ34_1: J34.1 R141.2 | length 405.3
  Top Layer w20: R141.2@8660,3215 8835.04,3215 8900.04,3280 8900.04,3415.39 J34.1@8897.95,3417.48
NetJ35_1: J35.1 R160.1 R162.1 U18.1 | length 313.6
  Top Layer w10: J35.1@6620,3435 6656.5,3471.5 R162.1@6656.5,3550.19 6685.19,3550.19 6704.19,3569.19 6734.63,3569.19 R160.1@6734.63,3471.84
NetJ35_2: J35.2 J36.2 R197.1 | length 666.8
  Top Layer w10: R197.1@6410,3968.5 6448.5,3968.5 6460,3980 J36.2@6525,3980
  Bottom Layer w10: J35.2@6520,3435 6520,3520 6525,3525 J36.2@6525,3980
NetJ36_1: J36.1 R166.1 R168.1 U18.7 | length 324.4
  Top Layer w10: J36.1@6625,3980 6731.31,3980 R168.1@6759.63,3951.68 R166.1@6759.63,3886.84 6759.63,3855.37 6785,3830 U18.7@6785,3784.13
NetJ37_1: J37.1 TP47.1 | length 212.2
  Top Layer w10: J37.1@5670,2131.85 5786.85,2131.85 5845,2190 TP47.1@5845,2176.85
NetJ37_2: J37.2 J39.1 R183.2 | length 412.8
  Top Layer w10: R183.2@5475,2240 5475,2295 5490,2310 5560,2310 5570,2320 ; J39.1@5570,2401.85 5570,2320 ; J37.2@5670,2231.85 5670,2290 5650,2310 5580,2310 5570,2320
NetJ38_1: J38.1 TP48.1 | length 479.6
  Bottom Layer w10: TP48.1@5790,2675 5905,2560 6040,2560 6104.99,2495.01 J38.1@6195,2495.01
NetJ38_2: J38.2 J40.1 R184.2 | length 484.5
  Top Layer w10: J40.1@6025,2375.01 6254.99,2375.01 6275,2375 ; R184.2@6290,2275 6290,2360 6275,2375 ; J38.2@6295,2495.01 6295,2395 6275,2375
NetJ39_2: J39.2 R173.1 | length 553.6
  Top Layer w10: J39.2@5470,2401.85 5470,2335 5395,2260 5395,2130 5445,2080 v1(5555,2080)
  Bottom Layer w10: v1(5555,2080) R173.1@5555,2150
NetJ40_2: J40.2 R174.1 | length 232.4
  Bottom Layer w10: J40.2@6025,2275.01 6114.99,2275.01 6130,2260 6130,2210 6144.99,2195.01 R174.1@6195,2195.01
NetJ41_1: J41.1 TP49.1 | length 276.9
  Top Layer w10: TP49.1@5130,2435 5130,2307 5190,2247 J41.1@5254,2247
NetJ42_1: J42.1 TP50.1 | length 379
  Top Layer w10: TP50.1@5850,2005 5920,2075 J42.1@6200,2075
NetJ45_2: J45.2 R177.1 | length 248.5
  Bottom Layer w10: J45.2@5985,2725 6075,2725 6085,2715 6085,2640 6101.95,2623.05 R177.1@6147.38,2623.05
NetJ46_2: J46.2 R178.1 | length 204.8
  Bottom Layer w10: J46.2@5985,3295 6065,3295 6075,3285 6075,3255 6095,3235 R178.1@6147.38,3235
NetL1_2: L1.2 R35.1 TP5.1 | length 229.1
  Top Layer w20: TP5.1@455,855 453.5,856.5 L1.2@453.5,1005 R35.1@532.01,1005
NetL2_2: L2.2 R41.1 TP43.1 | length 292.4
  Top Layer w20: R41.1@532.01,1280 L2.2@453.51,1280 453.51,1166.49 475,1145 TP43.1@545,1145
NetL5_2: L5.2 R89.1 TP25.1 | length 487.2
  Top Layer w20: R89.1@2332.35,827.59 2332.35,756.15 L5.2@2334.41,754.09 2390.91,754.09 2420,725 2420,530 TP25.1@2335,445
NetL6_2: L6.2 R95.1 TP59.1 | length 468.6
  Top Layer w20: TP59.1@2035,445 2035,530 1980,585 1980,730 2004.09,754.09 L6.2@2059.41,754.09 R95.1@2059.41,825.53
NetL7_2: L7.2 R106.1 TP6.1 | length 410.2
  Top Layer w20: R106.1@6890.12,1192.36 L7.2@6890.12,1118.86 6956.14,1118.86 6980,1095 6980,950 TP6.1@6915,885
NetL8_2: L8.2 R112.1 TP60.1 | length 208.6
  Top Layer w20: L8.2@6630.12,1118.86 R112.1@6630.12,1192.36 6672.36,1192.36 6685,1205 TP60.1@6760,1205
NetL9_2: L9.2 R122.1 TP38.1 | length 476.4
  Top Layer w20: R122.1@8512.99,1515 L9.2@8591.5,1515 8591.5,1570 8611.5,1590 8745,1590 8820,1515 TP38.1@8895,1515
NetL10_2: L10.2 R128.1 TP61.1 | length 461
  Top Layer w20: R128.1@8512.99,1235 L10.2@8591.5,1235 8591.5,1188.5 8610,1170 8725,1170 8785,1230 TP61.1@8895,1230
NetL11_2: L11.2 R207.1 | length 82
  Top Layer w20: L11.2@925,3070 R207.1@1007.01,3070
NetL12_2: L12.2 R211.1 | length 83.5
  Top Layer w20: L12.2@925,2413.5 R211.1@1008.5,2413.5
NetL13_2: L13.2 R206.1 | length 83.5
  Top Layer w20: L13.2@925,3165 R206.1@1008.5,3165
NetL14_2: L14.2 R210.1 | length 83.5
  Top Layer w20: L14.2@925,2508.5 R210.1@1008.5,2508.5
NetL15_2: L15.2 R217.1 | length 83.5
  Top Layer w20: R217.1@8041.5,2875 L15.2@8125,2875
NetL16_2: L16.2 R223.1 | length 78.5
  Top Layer w20: R223.1@8046.5,3525 L16.2@8125,3525
NetL17_2: L17.2 R216.1 | length 83.5
  Top Layer w20: R216.1@8041.5,2785 L17.2@8125,2785
NetL18_2: L18.2 R222.1 | length 83.5
  Top Layer w20: R222.1@8041.5,3435 L18.2@8125,3435
NetR2_1: R2.1 R5.2 | length 115.8
  Top Layer w20: R2.1@272.09,3480.91 R5.2@387.91,3480.91
NetR4_1: R4.1 R7.2 | length 110.8
  Top Layer w20: R4.1@509.17,2730 R7.2@620,2730
NetR5_1: R5.1 R11.2 | length 114.1
  Top Layer w20: R5.1@497.09,3482.91 607.09,3482.91 R11.2@610,3480
NetR6_2: R6.2 U20.7 | length 733.9
  Top Layer w10: U20.7@1859.57,3095 1906,3095 1950,3051 1950,2945 1982,2913 2387,2913 2411.63,2888.37 R6.2@2411.63,2854.21
NetR7_1: R7.1 R16.2 | length 110.8
  Top Layer w20: R7.1@734.17,2730 R16.2@845,2730
NetR9_2: R9.2 U21.7 | length 612.6
  Top Layer w10: U21.7@1859.17,2515.63 v1(1925.87,2515.63) ; v1(2313.5,2253.5) R9.2@2313.5,2303.19
  Bottom Layer w10: v1(1925.87,2515.63) 1968.66,2515.63 2230.78,2253.5 v1(2313.5,2253.5)
NetR12_1: R12.1 R14.2 R15.2 U1.3 | length 244.4
  Top Layer w10: R15.2@2278.88,2858.35 R14.2@2278.88,2788.35 2281.75,2791.22 R12.1@2347.38,2791.22 2347.38,2748.34 2357.38,2738.35 U1.3@2357.38,2690.63
NetR12_2: R12.2 U20.6 | length 639.1
  Top Layer w10: U20.6@1859.57,3045 1908,3045 1923,3030 1923,2935 1964,2894 2336,2894 2347.38,2882.62 R12.2@2347.38,2854.21
NetR13_1: R13.1 R17.2 R18.2 U1.5 | length 328.3
  Top Layer w10: R17.2@2212.38,2461.85 2182.38,2431.85 R18.2@2182.38,2366.18 R13.1@2247.38,2366.18 2247.38,2403.35 2257.38,2413.35 2292.38,2413.35 2307.38,2428.34 U1.5@2307.38,2476.06
NetR13_2: R13.2 U21.6 | length 550
  Top Layer w10: U21.6@1859.17,2465.63 1914.37,2465.63 2155,2225 2220,2225 2247.38,2252.38 R13.2@2247.38,2303.19
NetR24_1: R24.1 R28.2 U2.2 | length 306.7
  Top Layer w10: U2.2@2382.59,3426.85 2382.59,3368.46 2413.33,3337.72 R24.1@2522.59,3337.72 2548.18,3363.31 R28.2@2607.59,3363.31
NetR30_1: R30.1 R34.2 U2.6 | length 288.5
  Top Layer w10: R34.2@2107.59,3249.14 2167,3249.14 R30.1@2192.59,3274.73 2316.32,3274.73 2332.59,3258.46 U2.6@2332.59,3212.29
NetR38_1: R38.1 U3.1 | length 140.3
  Top Layer w10: U3.1@870.32,1217.52 928.28,1217.52 946.1,1235.34 R38.1@946.1,1292.52
NetR38_2: R38.2 U3.8 | length 139.8
  Top Layer w10: R38.2@1009.09,1292.52 1009.09,1236.34 1027.92,1217.52 U3.8@1084.88,1217.52
NetR42_2: R42.2 R44.2 R62.1 | length 137.6
  Top Layer w10: R42.2@1294.51,1100.28 R62.1@1294.51,1035.28 1365.47,1035.28 R44.2@1366.59,1036.4
NetR46_1: R46.1 R47.2 R48.2 U4.3 | length 293.2
  Top Layer w10: R47.2@1429.59,834.27 R48.2@1429.59,904.27 1429.59,970.2 1474.02,970.2 1488.09,984.27 1488.09,1014.27 1505.04,1031.22 U4.3@1544,1031.22
NetR46_2: R46.2 R57.1 | length 72
  Top Layer w10: R57.1@1294.51,970.28 R46.2@1366.52,970.28
NetR63_1: R63.1 U5.18 | length 261.3
  Top Layer w8: R63.1@7835.12,413.86 7876.12,413.86 7904.12,441.86 7904.12,519.86 7918.71,534.45 U5.18@8000.79,534.45
NetR64_2: R64.2 R65.1 R67.2 | length 135
  Top Layer w20: R65.1@7637.13,628.86 R64.2@7772.13,628.86
NetR69_1: R69.1 U5.21 | length 263.2
  Top Layer w8: R69.1@7923.94,369.53 7923.94,403.86 7938.94,418.86 8050.12,418.86 8065.75,434.49 U5.21@8065.75,508.86
NetR72_1: R72.1 R73.1 R77.2 U9.1 | length 271.7
  Top Layer w20: R77.2@4254,2870.5 R73.1@4324,2870.5 4324,2842 4349,2817 ; R72.1@4337.15,2767.75 4337.15,2805.15 4349,2817 ; U9.1@4396.6,2857.55 4396.6,2824.6 4389,2817 4349,2817
NetR72_2: R72.2 R78.2 R81.1 R189.2 R192.2 R193.2 R194.2 R195.2 | length 889.8
  Top Layer w20: R194.2@4325.5,2542 4399,2542 4419,2562 4419,2592 ; R193.2@4325.5,2612 4399,2612 4419,2592 ; R72.2@4337.15,2704.76 R78.2@4407.15,2704.76 4407.15,2667 4417.15,2657 4504,2657 4517.5,2643.5 ; R195.2@4517.5,2547 R81.1@4517.5,2607 ; R189.2@4659,2705.5 4610.5,2657 4531.01,2657 4517.5,2643.5 ; R189.2@4669,2705.5 R192.2@4729,2705.5 ; 4419,2592 4434,2607 R81.1@4517.5,2607 ; R81.1@4517.5,2607 4517.5,2643.5
NetR73_2: R73.2 R242.1 U9.4 | length 285.5
  Top Layer w20: R73.2@4324,2933.5 4362.5,2933.5 4384.31,2911.69 4448.69,2911.69 4471.4,2934.4 U9.4@4471.4,2965.82 4471.4,3052.1 R242.1@4470,3053.5
NetR82_1: R82.1 U11.5 | length 106
  Top Layer w10: U11.5@4859.65,1594.17 4859.65,1694.45 R82.1@4863.7,1698.5
NetR92_1: R92.1 U13.1 | length 144.3
  Top Layer w10: R92.1@2054.41,1243.14 2118.29,1243.14 2129.41,1232.02 U13.1@2129.41,1167.36
NetR92_2: R92.2 U13.8 | length 144.9
  Top Layer w10: R92.2@2054.41,1306.14 2119.39,1306.14 2129.41,1316.15 U13.8@2129.41,1381.92
NetR96_1: R96.1 R98.2 R105.1 | length 149.3
  Top Layer w10: R98.2@1927.44,964.27 1899.41,936.24 R96.1@1899.41,891.54 R105.1@1964.41,891.54
NetR100_1: R100.1 R101.2 R102.2 U4.5 | length 266.2
  Top Layer w10: U4.5@1758.57,981.22 1720.87,981.22 1701.59,961.95 R100.1@1701.59,904.27 1699.41,902.09 R101.2@1699.41,831.59 R102.2@1769.41,831.59
NetR100_2: R100.2 R104.1 | length 75.1
  Top Layer w10: R100.2@1764.59,904.27 1770.67,898.19 1827.81,898.19 R104.1@1834.41,891.59
NetR109_1: R109.1 U6.1 | length 141.3
  Top Layer w10: R109.1@6600.43,1609.76 6659.21,1609.76 6675.43,1593.55 U6.1@6675.43,1533.98
NetR109_2: R109.2 U6.8 | length 141.2
  Top Layer w10: R109.2@6600.43,1672.76 6659.02,1672.76 6675.43,1689.17 U6.8@6675.43,1748.54
NetR113_1: R113.1 R119.2 | length 72.2
  Top Layer w10: R113.1@7134.7,1392.2 7206.16,1392.2 R119.2@7206.71,1391.65
NetR114_1: R114.1 R116.2 R117.2 | length 137.6
  Top Layer w10: R114.1@7134.7,1522.2 R116.2@7134.7,1457.2 7135.82,1458.32 R117.2@7206.79,1458.32
NetR119_1: R119.1 R120.2 R121.2 U14.3 | length 287.2
  Top Layer w10: R120.2@7269.78,1256.2 R121.2@7269.78,1326.2 7269.7,1326.27 R119.1@7269.7,1391.65 7302.91,1391.65 7325.12,1413.86 7325.12,1433.86 7344.41,1453.15 U14.3@7384.2,1453.15
NetR125_1: R125.1 U15.1 | length 146.2
  Top Layer w10: R125.1@8096.61,1211.65 8096.61,1275.35 8112.91,1291.65 U15.1@8172.4,1291.65
NetR125_2: R125.2 U15.8 | length 146.2
  Top Layer w10: U15.8@7957.83,1291.65 8017.32,1291.65 8033.62,1275.35 R125.2@8033.62,1211.65
NetR129_1: R129.1 R135.2 | length 70
  Top Layer w10: R135.2@7570.31,1318.86 7635.32,1318.86 R129.1@7638.82,1315.35
NetR130_1: R130.1 R132.1 R133.2 | length 136.3
  Top Layer w10: R132.1@7703.82,1315.35 R130.1@7768.82,1315.35 7767.64,1316.54 R133.2@7767.64,1386.2
NetR135_1: R135.1 R136.2 R137.2 U14.5 | length 297.7
  Top Layer w10: R136.2@7440.12,1320.35 7441.61,1318.86 R135.1@7507.32,1318.86 ; R137.2@7507.32,1253.86 R135.1@7507.32,1318.86 ; U14.5@7598.77,1403.15 7525.86,1403.15 7507.32,1384.61 R135.1@7507.32,1318.86
NetR139_1: R139.1 R142.2 | length 110.8
  Top Layer w20: R142.2@8435,2545 R139.1@8545.83,2545
NetR141_1: R141.1 R144.2 | length 110.8
  Top Layer w20: R144.2@8435,3215 R141.1@8545.83,3215
NetR142_1: R142.1 R148.2 | length 115.8
  Top Layer w20: R148.2@8205,2545 R142.1@8320.83,2545
NetR143_2: R143.2 U22.7 | length 662.6
  Top Layer w10: R143.2@6781.71,2672.83 6781.71,2620.29 v1(6782,2620) ; v1(7202,2795) U22.7@7270.43,2795
  Bottom Layer w10: v1(6782,2620) 6809,2593 7045,2593 7115,2663 7115,2708 v1(7202,2795)
NetR144_1: R144.1 R153.2 | length 121
  Top Layer w20: R153.2@8199.96,3215.43 8200.39,3215 R144.1@8320.83,3215
NetR146_2: R146.2 U23.7 | length 538
  Top Layer w10: R146.2@6844.84,3223.85 6850.87,3223.85 6850.87,3270 6875.87,3295 7030,3295 7165,3430 U23.7@7270.43,3430
NetR149_1: R149.1 R151.2 R152.2 U17.3 | length 288.2
  Top Layer w10: U17.3@6835.96,2836.42 6835.96,2799.04 6850,2785 ; R152.2@6845.96,2735.82 6840,2741.78 6840,2775 6850,2785 ; R151.2@6914.46,2668.7 R149.1@6914.46,2738.7 6914.46,2775.54 6905,2785 6850,2785
NetR149_2: R149.2 U22.6 | length 337
  Top Layer w10: R149.2@6977.45,2738.7 7023.7,2738.7 7130,2845 U22.6@7270.43,2845
NetR150_1: R150.1 R154.2 R155.2 U17.5 | length 283.3
  Top Layer w10: U17.5@6885.96,3050.98 6885.96,3095.96 6910.96,3120.96 R150.1@6910.96,3160.86 6979.49,3160.86 R155.2@6980,3160.35 R154.2@6980,3066.5
NetR150_2: R150.2 U23.6 | length 517.4
  Top Layer w10: v1(6910,3265) 6910.96,3264.04 R150.2@6910.96,3223.85 ; v1(7210,3480) U23.6@7270.43,3480
  Bottom Layer w10: v1(6910,3265) 7040,3265 7210,3435 v1(7210,3480)
NetR161_1: R161.1 R165.2 U18.2 | length 307.9
  Top Layer w10: R165.2@6560,3633.1 6619.41,3633.1 R161.1@6645,3658.69 6756.31,3658.69 6785,3630 U18.2@6785,3569.56
NetR167_1: R167.1 R171.2 U18.6 | length 287.3
  Top Layer w10: U18.6@6835,3784.13 6835,3740 6853.32,3721.68 R167.1@6975,3721.68 7000.59,3747.27 R171.2@7060,3747.27
NetR189_1: R189.1 R190.1 R191.2 U16.1 | length 280.5
  Top Layer w20: R191.2@4589,2860.5 R190.1@4659,2860.5 4659,2827 4674,2812 ; R189.1@4659,2768.5 4659,2797 4674,2812 ; U16.1@4741.6,2857.87 4741.6,2824.6 4729,2812 4674,2812
NetR190_2: R190.2 R243.1 U16.4 | length 268.6
  Top Layer w20: R190.2@4659,2923.5 4805.5,2923.5 4816.4,2934.4 U16.4@4816.4,2966.13 4816.4,2998.4 4825,3007 R243.1@4825,3037.5
NetR193_1: R193.1 U19.2 | length 68.2
  Top Layer w20: U19.2@4261.4,2679.76 4261.4,2613.1 R193.1@4262.5,2612
NetR194_1: R194.1 TP56.1 | length 115.2
  Top Layer w20: TP56.1@4262,2427 4262.5,2427.5 R194.1@4262.5,2542
NetR195_1: R195.1 U10.6 | length 99.7
  Top Layer w15: R195.1@4580.5,2547 4629.39,2498.1 U10.6@4629.39,2467.6
NetR202_1: R202.1 R220.2 U26.2 | length 469.4
  Top Layer w8: v1(5343.5,620) 5354.13,630.63 U26.2@5354.13,652.44
  Top Layer w20: v1(5157.01,670) R220.2@5157.01,765 5157.01,823.5 5173.5,840 R202.1@5222.01,840
  Bottom Layer w20: v1(5157.01,670) 5293.5,670 v1(5343.5,620)
NetR203_1: R203.1 TP1.1 | length 83.5
  Top Layer w10: TP1.1@5138.5,435 R203.1@5138.5,518.5
NetR203_2: R203.2 U26.1 | length 250.8
  Top Layer w8: R203.2@5138.5,581.5 v1(5138.5,625) ; v1(5293.5,625) 5320.94,652.44 U26.1@5334.45,652.44
  Bottom Layer w8: v1(5138.5,625) v1(5293.5,625)
NetR204_1: R204.1 R232.2 U26.7 | length 157.7
  Top Layer w9: U26.7@5432.87,727.24 5455.75,727.24
  Top Layer w20: 5455.75,727.24 5478.5,750 R232.2@5517.01,750 5518.5,748.5 R204.1@5518.5,686.5
NetR207_2: R207.2 R208.2 R209.2 | length 140.6
  Top Layer w20: R208.2@1005,3001.5 R209.2@1075,3001.5 1070,3006.5 R207.2@1070,3070
NetR211_2: R211.2 R212.2 R213.2 | length 150
  Top Layer w20: R213.2@1005,2335 R212.2@1075,2335 1071.5,2338.5 R211.2@1071.5,2413.5
NetR214_2: R214.2 U26.12 | length 336.4
  Top Layer w8: v1(5273.5,740) 5278.5,740 5288.5,730 5331.69,730 U26.12@5334.45,727.24 ; R214.2@5353.5,890 v1(5353.5,933.5)
  Bottom Layer w8: v1(5273.5,740) 5353.5,820 v1(5353.5,933.5)
NetR217_2: R217.2 R218.2 R219.2 | length 139.1
  Top Layer w20: R217.2@7978.5,2875 7978.5,2947.01 R218.2@7980,2948.5 R219.2@8045,2948.5
NetR223_2: R223.2 R224.2 R225.2 | length 139.1
  Top Layer w20: R223.2@7983.5,3525 7983.5,3597.01 R224.2@7985,3598.5 R225.2@8050,3598.5
NetR231_2: R231.2 U26.8 | length 141.5
  Top Layer w8: U26.8@5413.19,727.24 5413.19,749.69 5433.5,770 5460,770 5485,795 R231.2@5485,823.5
NetR238_2: R238.2 U27.2 | length 133
  Top Layer w8: R238.2@3530,333.58 3530,372.09 3545,387.09 3565,387.09 3585.31,407.4 U27.2@3585.31,431.97
NetR239_1: R239.1 U27.8 | length 259.9
  Top Layer w9: U27.8@3605,542.2 3605,587.09
  Top Layer w20: 3605,587.09 R239.1@3605,802.09
NetR244_2: R244.2 U25.5 | length 243.9
  Top Layer w20: R244.2@2366.5,3675 2430,3675 2445,3690 2445,3765 2425,3785 U25.5@2369.13,3785
NetT5_1: T5.1 U25.3 | length 469.8
  Top Layer w20: T5.1@1862.64,3574.92 2034.92,3574.92 2207.6,3747.6 U25.3@2260.87,3747.6
NetT5_3: T5.3 U25.1 | length 473.8
  Top Layer w20: T5.3@1862.64,3815.08 1875.08,3815.08 1970,3910 2125,3910 2212.6,3822.4 U25.1@2260.87,3822.4
NetTP17_1: TP17.1 U5.7 | length 378.6
  Top Layer w8: U5.7@8124.8,658.46 8124.8,703.54 8165.12,743.86 8337.12,743.86 8360.12,766.86 TP17.1@8360.12,838.86
PD_OUT1: C4.1 J8.3 R8.2 | length 1334.8
  Top Layer w10: R8.2@2546.08,2628.5 v1(2596.23,2628.5) 2652.5,2628.5 2718,2694 2718,2947 2785,3014 3110,3014 3159,3063 3246,3063 3304,3121 3304,3172 3281,3195 J8.3@3190,3195
  Bottom Layer w10: C4.1@2546.08,2628.5 v1(2596.23,2628.5)
PD_OUT1_ZC: R26.1 R229.1 | length 130.4
  Top Layer w10: R229.1@2020,3520.5 2046.5,3520.5 2057,3510 2057,3462 2064.43,3454.57 R26.1@2094.98,3454.57
PD_OUT2: C5.1 J9.3 R10.2 | length 858.2
  Top Layer w20: R10.2@2513.5,2303.5 v1(2562.01,2303.5) 2814.5,2556 3039,2556 3108,2625 J9.3@3190,2625
  Bottom Layer w20: C5.1@2513.5,2303.5 v1(2562.01,2303.5)
PD_OUT2_ZC: R32.1 R230.1 | length 123.5
  Top Layer w10: R230.1@2075,3111.5 2102.5,3111.5 2111,3103 2111,3059 2121.93,3048.07 R32.1@2146.48,3048.07
PD_OUT3: C104.1 J45.3 R145.2 | length 1179.5
  Top Layer w10: R145.2@6647.26,2898.54 6698.54,2898.54 v1(6700,2900)
  Bottom Layer w10: J45.3@5985,2625 6060,2625 6115,2570 6380,2570 6405,2595 6405,2850 6500,2945 6675,2945 6700,2920 v1(6700,2900) 6698.54,2898.54 C104.1@6647.26,2898.54
PD_OUT3_ZC: R163.1 R200.1 | length 1202
  Top Layer w10: R200.1@6575,2898.54 6540,2933.54 6540,3300 6575,3335 7020,3335 7120,3435 7120,3535 7113.32,3541.68 R163.1@7072.62,3541.68
PD_OUT4: C105.1 J46.3 R147.2 | length 717.7
  Top Layer w10: v1(6600,3223.54) R147.2@6644.84,3223.54
  Bottom Layer w10: J46.3@5985,3195 6340,3195 6370,3225 6598.54,3225 v1(6600,3223.54) C105.1@6644.84,3223.54
PD_OUT4_ZC: R169.1 R201.1 | length 1010.8
  Top Layer w10: R201.1@6776.5,3295 6802,3295 6817,3310 v1(6850,3310) ; R169.1@7021.12,3948.18 7073.18,3948.18 v1(7075,3950)
  Bottom Layer w10: v1(6850,3310) 7045,3310 7110,3375 7110,3520 7075,3555 v1(7075,3950)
